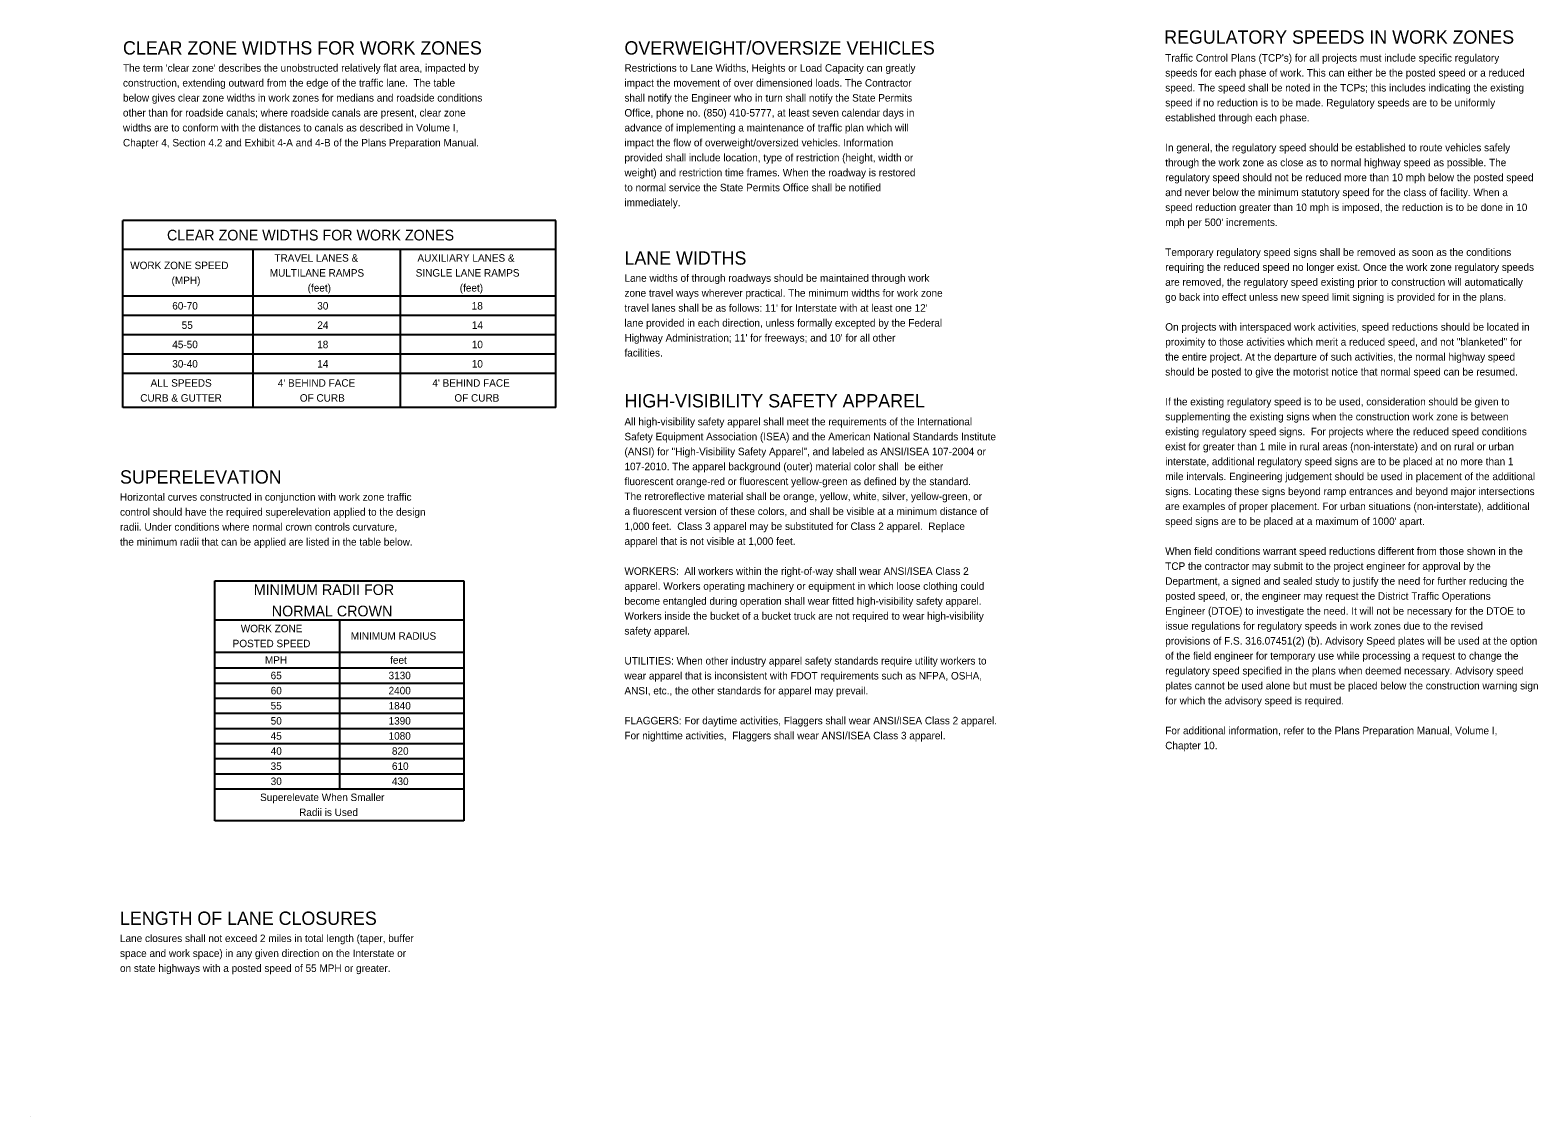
# Model space of a CAD drawing. Extents: x 10000 to 10706, y 10000 to 10509.
import ezdxf

# ---------------------------------------------------------------- set-up
doc = ezdxf.new("R2010")
doc.units = 0
doc.layers.add('Patterning', color=7, linetype='Continuous')
doc.layers.add('PlotBorder_dp', color=7, linetype='Continuous')

msp = doc.modelspace()

# ---------------------------------------------------------------- linework, layer by layer
at = {"layer": 'Patterning'}
msp.add_line((10000, 10000), (10000, 10000), dxfattribs=at)
msp.add_line((10000, 10000), (10000, 10000), dxfattribs=at)
at = {"layer": 'PlotBorder_dp'}
for p, q in [((10246.24, 10419.67), (10043.48, 10419.67)), ((10043.48, 10332.21), (10043.48, 10419.67)), ((10246.24, 10332.23), (10246.24, 10419.67)), ((10246.24, 10406.08), (10043.48, 10406.08)), ((10104.52, 10332.21), (10104.52, 10406.08)), ((10173.51, 10332.23), (10173.51, 10406.08)), ((10246.24, 10384.31), (10043.48, 10384.31)), ((10246.24, 10375.26), (10043.48, 10375.26)), ((10246.24, 10366.2), (10043.48, 10366.2)), ((10246.24, 10357.14), (10043.48, 10357.14)), ((10246.24, 10348.08), (10043.48, 10348.08)), ((10246.24, 10332.23), (10043.48, 10332.23)), ((10086.5, 10250.92), (10203.22, 10250.92)), ((10086.5, 10138.65), (10086.5, 10250.92)), ((10203.22, 10250.92), (10203.22, 10138.65)), ((10086.5, 10232.79), (10203.22, 10232.79)), ((10144.86, 10232.79), (10144.86, 10153.6)), ((10086.5, 10217.59), (10203.22, 10217.59)), ((10086.5, 10210.22), (10203.22, 10210.22)), ((10086.5, 10203.14), (10203.22, 10203.14)), ((10086.5, 10196.06), (10203.22, 10196.06)), ((10086.5, 10188.98), (10203.22, 10188.98)), ((10086.5, 10181.91), (10203.22, 10181.91)), ((10086.5, 10174.83), (10203.22, 10174.83)), ((10086.5, 10167.75), (10203.22, 10167.75)), ((10086.5, 10160.67), (10203.22, 10160.67)), ((10086.5, 10153.6), (10203.22, 10153.6)), ((10203.22, 10138.65), (10086.5, 10138.65))]:
    msp.add_line(p, q, dxfattribs=at)

# ---------------------------------------------------------------- texts
for s, height, p in [('CLEAR ZONE WIDTHS FOR WORK ZONES', 6.25, (10043.48, 10497.44)), ('OVERWEIGHT/OVERSIZE VEHICLES', 6.25, (10278.4, 10497.44)), ('REGULATORY SPEEDS IN WORK ZONES', 6.25, (10531.22, 10502.51)), ("Traffic Control Plans (TCP's) for all projects must include specific regulatory ", 3.5, (10531.73, 10494.14)), ("The term 'clear zone' describes the unobstructed relatively flat area, impacted by ", 3.5, (10043.48, 10489.42)), ('speeds for each phase of work. This can either be the posted speed or a reduced ', 3.5, (10531.73, 10487.14)), ('construction, extending outward from the edge of the traffic lane.  The table ', 3.5, (10043.48, 10482.42)), ('speed. The speed shall be noted in the TCPs; this includes indicating the existing ', 3.5, (10531.73, 10480.14)), ('below gives clear zone widths in work zones for medians and roadside conditions ', 3.5, (10043.48, 10475.42)), ('speed if no reduction is to be made. Regulatory speeds are to be uniformly ', 3.5, (10531.73, 10473.14)), ('other than for roadside canals; where roadside canals are present, clear zone ', 3.5, (10043.48, 10468.42)), ('established through each phase.', 3.5, (10531.73, 10466.14)), ('widths are to conform with the distances to canals as described in Volume I, ', 3.5, (10043.48, 10461.42)), ('Chapter 4, Section 4.2 and Exhibit 4-A and 4-B of the Plans Preparation Manual. ', 3.5, (10043.48, 10454.42)), ('In general, the regulatory speed should be established to route vehicles safely ', 3.5, (10531.73, 10452.14)), ('through the work zone as close as to normal highway speed as possible. The ', 3.5, (10531.73, 10445.14)), ('regulatory speed should not be reduced more than 10 mph below the posted speed ', 3.5, (10531.73, 10438.14)), ('and never below the minimum statutory speed for the class of facility. When a ', 3.5, (10531.73, 10431.14)), ('speed reduction greater than 10 mph is imposed, the reduction is to be done in 10 ', 3.5, (10531.73, 10424.14)), ("mph per 500' increments.", 3.5, (10531.73, 10417.14)), ('CLEAR ZONE WIDTHS FOR WORK ZONES', 5, (10064.11, 10410.38)), ('TRAVEL LANES &', 3.5, (10114.4, 10400.45)), ('AUXILIARY LANES & ', 3.5, (10181.42, 10400.45)), ('LANE WIDTHS', 6.25, (10278.4, 10399.04)), ('Temporary regulatory speed signs shall be removed as soon as the conditions ', 3.5, (10531.73, 10403.14)), ('WORK ZONE SPEED', 3.5, (10046.87, 10396.95)), ('MULTILANE RAMPS', 3.5, (10112.24, 10393.45)), ('SINGLE LANE RAMPS', 3.5, (10180.61, 10393.45)), ('requiring the reduced speed no longer exist. Once the work zone regulatory speeds ', 3.5, (10531.73, 10396.14)), ('(MPH)', 3.5, (10066.24, 10389.95)), ('(feet)', 3.5, (10130, 10386.45)), ('(feet)', 3.5, (10201.24, 10386.45)), ('are removed, the regulatory speed existing prior to construction will automatically ', 3.5, (10531.73, 10389.14)), ('go back into effect unless new speed limit signing is provided for in the plans.', 3.5, (10531.73, 10382.14)), ('60-70', 3.5, (10066.57, 10378.03)), ('30', 3.5, (10134.49, 10378.03)), ('18', 3.5, (10206.85, 10378.03)), ('55', 3.5, (10070.98, 10368.98)), ('24', 3.5, (10134.52, 10368.98)), ('14', 3.5, (10206.9, 10368.98)), ('On projects with interspaced work activities, speed reductions should be located in ', 3.5, (10531.73, 10368.14)), ('45-50', 3.5, (10066.57, 10359.92)), ('18', 3.5, (10134.46, 10359.92)), ('10', 3.5, (10206.88, 10359.92)), ('proximity to those activities which merit a reduced speed, and not "blanketed" for ', 3.5, (10531.73, 10361.14)), ('30-40', 3.5, (10066.57, 10350.86)), ('14', 3.5, (10134.52, 10350.86)), ('10', 3.5, (10206.88, 10350.86)), ('the entire project. At the departure of such activities, the normal highway speed ', 3.5, (10531.73, 10354.14)), ('should be posted to give the motorist notice that normal speed can be resumed.', 3.5, (10531.73, 10347.14)), ('ALL SPEEDS', 3.5, (10056.42, 10341.9)), ("4' BEHIND FACE", 3.5, (10116.02, 10341.9)), ("4' BEHIND FACE", 3.5, (10188.41, 10341.9)), ('CURB & GUTTER ', 3.5, (10051.57, 10334.9)), ('OF CURB', 3.5, (10126.33, 10334.9)), ('OF CURB', 3.5, (10198.72, 10334.9)), ('HIGH-VISIBILITY SAFETY APPAREL', 6.25, (10278.4, 10332.18)), ('If the existing regulatory speed is to be used, consideration should be given to ', 3.5, (10531.73, 10333.14)), ('All high-visibility safety apparel shall meet the requirements of the International ', 3.5, (10278.4, 10323.8)), ('supplementing the existing signs when the construction work zone is between ', 3.5, (10531.73, 10326.14)), ('Safety Equipment Association (ISEA) and the American National Standards Institute ', 3.5, (10278.4, 10316.8)), ('existing regulatory speed signs.  For projects where the reduced speed conditions ', 3.5, (10531.73, 10319.14)), ('(ANSI) for "High-Visibility Safety Apparel", and labeled as ANSI/ISEA 107-2004 or ', 3.5, (10278.4, 10309.8)), ('exist for greater than 1 mile in rural areas (non-interstate) and on rural or urban ', 3.5, (10531.73, 10312.14)), ('107-2010. The apparel background (outer) material color shall  be either ', 3.5, (10278.4, 10302.8)), ('interstate, additional regulatory speed signs are to be placed at no more than 1 ', 3.5, (10531.73, 10305.14)), ('SUPERELEVATION', 6.25, (10042.09, 10296.52)), ('fluorescent orange-red or fluorescent yellow-green as defined by the standard.  ', 3.5, (10278.4, 10295.8)), ('mile intervals. Engineering judgement should be used in placement of the additional ', 3.5, (10531.73, 10298.14)), ('Horizontal curves constructed in conjunction with work zone traffic', 3.5, (10042.09, 10288.5)), ('The retroreflective material shall be orange, yellow, white, silver, yellow-green, or ', 3.5, (10278.4, 10288.8)), ('signs. Locating these signs beyond ramp entrances and beyond major intersections ', 3.5, (10531.73, 10291.14)), ('control should have the required superelevation applied to the design', 3.5, (10042.09, 10281.5)), ('a fluorescent version of these colors, and shall be visible at a minimum distance of ', 3.5, (10278.4, 10281.8)), ('are examples of proper placement. For urban situations (non-interstate), additional ', 3.5, (10531.73, 10284.14)), ('radii. Under conditions where normal crown controls curvature,', 3.5, (10042.09, 10274.5)), ('1,000 feet.  Class 3 apparel may be substituted for Class 2 apparel.  Replace ', 3.5, (10278.4, 10274.8)), ("speed signs are to be placed at a maximum of 1000' apart.", 3.5, (10531.73, 10277.14)), ('the minimum radii that can be applied are listed in the table below.', 3.5, (10042.09, 10267.5)), ('apparel that is not visible at 1,000 feet.', 3.5, (10278.4, 10267.8)), ('When field conditions warrant speed reductions different from those shown in the ', 3.5, (10531.73, 10263.14)), ('WORKERS:  All workers within the right-of-way shall wear ANSI/ISEA Class 2 ', 3.5, (10278.4, 10253.8)), ('TCP the contractor may submit to the project engineer for approval by the ', 3.5, (10531.73, 10256.14)), ('MINIMUM RADII FOR', 5, (10104.76, 10244.36)), ('apparel. Workers operating machinery or equipment in which loose clothing could ', 3.5, (10278.4, 10246.8)), ('Department, a signed and sealed study to justify the need for further reducing the ', 3.5, (10531.73, 10249.14)), ('become entangled during operation shall wear fitted high-visibility safety apparel. ', 3.5, (10278.4, 10239.8)), ('posted speed, or, the engineer may request the District Traffic Operations ', 3.5, (10531.73, 10242.14)), ('NORMAL CROWN', 5, (10113.2, 10234.36)), ('Workers inside the bucket of a bucket truck are not required to wear high-visibility ', 3.5, (10278.4, 10232.8)), ('Engineer (DTOE) to investigate the need. It will not be necessary for the DTOE to ', 3.5, (10531.73, 10235.14)), ('WORK ZONE', 3.5, (10098.67, 10226.91)), ('MINIMUM RADIUS', 3.5, (10150.18, 10223.41)), ('safety apparel.', 3.5, (10278.4, 10225.8)), ('issue regulations for regulatory speeds in work zones due to the revised ', 3.5, (10531.73, 10228.14)), ('POSTED SPEED', 3.5, (10094.85, 10219.91)), ('provisions of F.S. 316.07451(2) (b). Advisory Speed plates will be used at the option ', 3.5, (10531.73, 10221.14)), ('MPH', 3.5, (10109.99, 10212.15)), ('feet', 3.5, (10168.64, 10212.15)), ('UTILITIES: When other industry apparel safety standards require utility workers to ', 3.5, (10278.4, 10211.8)), ('of the field engineer for temporary use while processing a request to change the ', 3.5, (10531.73, 10214.14)), ('65', 3.5, (10112.65, 10204.93)), ('3130', 3.5, (10167.9, 10204.93)), ('wear apparel that is inconsistent with FDOT requirements such as NFPA, OSHA, ', 3.5, (10278.4, 10204.8)), ('regulatory speed specified in the plans when deemed necessary. Advisory speed ', 3.5, (10531.73, 10207.14)), ('60', 3.5, (10112.68, 10197.85)), ('2400', 3.5, (10167.9, 10197.85)), ('ANSI, etc., the other standards for apparel may prevail.  ', 3.5, (10278.4, 10197.8)), ('plates cannot be used alone but must be placed below the construction warning sign ', 3.5, (10531.73, 10200.14)), ('55', 3.5, (10112.65, 10190.77)), ('1840', 3.5, (10167.9, 10190.77)), ('for which the advisory speed is required.', 3.5, (10531.73, 10193.14)), ('50', 3.5, (10112.68, 10183.69)), ('1390', 3.5, (10167.9, 10183.69)), ('FLAGGERS: For daytime activities, Flaggers shall wear ANSI/ISEA Class 2 apparel. ', 3.5, (10278.4, 10183.8)), ('45', 3.5, (10112.65, 10176.62)), ('1080', 3.5, (10167.9, 10176.62)), ('For nighttime activities,  Flaggers shall wear ANSI/ISEA Class 3 apparel.', 3.5, (10278.4, 10176.8)), ('For additional information, refer to the Plans Preparation Manual, Volume I, ', 3.5, (10531.73, 10179.14)), ('40', 3.5, (10112.68, 10169.54)), ('820', 3.5, (10169.47, 10169.54)), ('Chapter 10.', 3.5, (10531.73, 10172.14)), ('35', 3.5, (10112.65, 10162.46)), ('610', 3.5, (10169.47, 10162.46)), ('30', 3.5, (10112.68, 10155.39)), ('430', 3.5, (10169.47, 10155.39)), ('Superelevate When Smaller ', 3.5, (10107.7, 10147.87)), ('Radii is Used', 3.5, (10126, 10140.87)), ('LENGTH OF LANE CLOSURES', 6.25, (10042.09, 10089.87))]:
    msp.add_text(s, height=height, dxfattribs=at).set_placement(p)
for s, p in [('Restrictions to Lane Widths, Heights or Load Capacity can greatly ', (10278.4, 10489.42)), ('impact the movement of over dimensioned loads. The Contractor ', (10278.4, 10482.42)), ('shall notify the Engineer who in turn shall notify the State Permits ', (10278.4, 10475.42)), ('Office, phone no. (850) 410-5777, at least seven calendar days in ', (10278.4, 10468.42)), ('advance of implementing a maintenance of traffic plan which will ', (10278.4, 10461.42)), ('impact the flow of overweight/oversized vehicles. Information ', (10278.4, 10454.42)), ('provided shall include location, type of restriction (height, width or ', (10278.4, 10447.42)), ('weight) and restriction time frames. When the roadway is restored ', (10278.4, 10440.42)), ('to normal service the State Permits Office shall be notified ', (10278.4, 10433.42)), ('immediately. ', (10278.4, 10426.42)), ('Lane widths of through roadways should be maintained through work ', (10278.4, 10391.03)), ('zone travel ways wherever practical. The minimum widths for work zone ', (10278.4, 10384.03)), ("travel lanes shall be as follows: 11' for Interstate with at least one 12' ", (10278.4, 10377.03)), ('lane provided in each direction, unless formally excepted by the Federal  ', (10278.4, 10370.03)), ("Highway Administration; 11' for freeways; and 10' for all other ", (10278.4, 10363.03)), ('facilities. ', (10278.4, 10356.03)), ('Lane closures shall not exceed 2 miles in total length (taper, buffer ', (10042.09, 10081.85)), ('space and work space) in any given direction on the Interstate or ', (10042.09, 10074.85)), ('on state highways with a posted speed of 55 MPH or greater. ', (10042.09, 10067.85))]:
    msp.add_text(s, height=3.5, rotation=359.99815, dxfattribs=at).set_placement(p)

doc.saveas('drawing.dxf')
